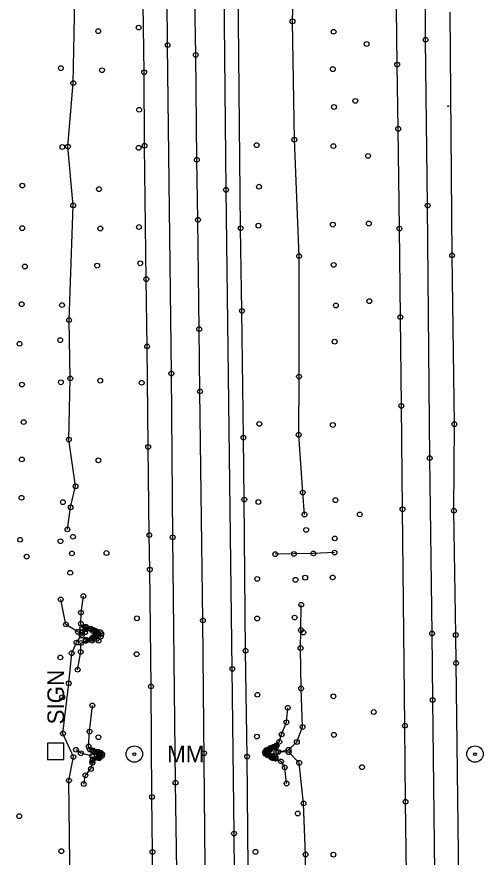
# Model space of a CAD drawing. Extents: x 20503438 to 20508873, y 7964251 to 7984667.
# Drawn here: x 20505333.3 to 20505528.3, y 7980569.8 to 7980921.4 of the extents above; entities that cross this region are included whole.
import ezdxf

# ---------------------------------------------------------------- set-up
doc = ezdxf.new("R2010")
doc.units = 0
for name, color, linetype in [('SurBreakLine', 7, 'Continuous'), ('SurConcreteSlab', 7, 'Continuous'), ('SurControl', 7, 'Continuous'), ('SurDikeDam', 7, 'Continuous'), ('SurDrainageArrowDown', 7, 'Continuous'), ('SurDrainageArrowUp', 7, 'Continuous'), ('SurEdgeRoadPaved', 7, 'Continuous'), ('SurEdgeShoulderPaved', 7, 'Continuous'), ('SurPointsNonDTM', 7, 'Continuous'), ('SurRoadPoints', 7, 'Continuous'), ('SurSurveyPoints', 7, 'Continuous')]:
    doc.layers.add(name, color=color, linetype=linetype)

msp = doc.modelspace()

# ---------------------------------------------------------------- linework, layer by layer
at = {"layer": 'SurBreakLine'}
for points in [[(20505502.82, 7979928.73), (20505501.16, 7980094.42), (20505500.7, 7980131.63), (20505500.35, 7980155.21), (20505500.03, 7980203.28), (20505500, 7980206.06), (20505499.27, 7980271.76), (20505498.89, 7980315.07), (20505498.72, 7980329.42), (20505496.74, 7980509.09), (20505496.18, 7980562.37), (20505495.83, 7980592.98), (20505495.56, 7980624.79), (20505494.56, 7980715.32), (20505494.07, 7980758.55), (20505493.65, 7980795.75), (20505493.28, 7980832.76), (20505492.74, 7980874.49), (20505492.33, 7980901.35), (20505491.27, 7980994.69)], [(20505418.93, 7979912.11), (20505417.39, 7980020.09), (20505416.54, 7980111.44), (20505416.16, 7980148.77), (20505415.87, 7980185.54), (20505415.61, 7980219.83), (20505414.98, 7980273.06), (20505413.7, 7980378.2), (20505413.25, 7980444.28), (20505412.62, 7980505.63), (20505412.46, 7980535.27), (20505412.01, 7980566.27), (20505411.1, 7980668.83), (20505409.87, 7980764.66), (20505409.52, 7980790.7), (20505409.02, 7980836.41), (20505408.56, 7980861.54), (20505408.11, 7980905.42), (20505407.63, 7980936.71)], [(20505358.71, 7980648.21), (20505360, 7980655.66), (20505360.09, 7980659.38), (20505362.08, 7980660.24), (20505364.7, 7980660.36), (20505367.46, 7980660.33), (20505368.33, 7980662.02), (20505368.64, 7980663.15), (20505368.18, 7980663.96), (20505366.63, 7980664.31), (20505365.38, 7980664.88), (20505364.19, 7980665.38), (20505362.16, 7980666.15), (20505362, 7980665.95), (20505360.66, 7980665.7), (20505360.07, 7980667.46), (20505360.12, 7980672.1), (20505361.13, 7980679.01)], [(20505361.28, 7980600.4), (20505361.96, 7980604.07), (20505364.25, 7980606.68), (20505364.86, 7980609.23), (20505364.89, 7980610.12), (20505367.74, 7980611.22), (20505368.79, 7980612.07), (20505368.96, 7980612.91), (20505368.3, 7980613.48), (20505367.34, 7980613.87), (20505363.86, 7980614.85), (20505363.29, 7980616.15), (20505363.69, 7980622.33), (20505364.86, 7980633.26)], [(20505446.07, 7980600.62), (20505445.32, 7980607.33), (20505443.76, 7980609.84), (20505441.48, 7980610.99), (20505440.46, 7980611.13), (20505439.6, 7980611.64), (20505438.2, 7980612.4), (20505437.31, 7980612.9), (20505437.04, 7980613.51), (20505437.24, 7980614.14), (20505437.83, 7980614.62), (20505439.22, 7980615.41), (20505440.71, 7980615.96), (20505441.56, 7980616.27), (20505441.96, 7980616.57), (20505443.03, 7980618.07), (20505444.02, 7980621.16), (20505446.03, 7980626.22), (20505446.58, 7980632.29)]]:
    msp.add_lwpolyline(points, dxfattribs=at)
at = {"layer": 'SurConcreteSlab'}
for points in [[(20505362.13, 7980665.18), (20505364.94, 7980664.43), (20505366.25, 7980664), (20505366.39, 7980663.87), (20505366.57, 7980663.36), (20505366.54, 7980662.54), (20505366.04, 7980662.17), (20505365.06, 7980661.69), (20505362.14, 7980660.73), (20505362.16, 7980660.37), (20505364.45, 7980661.16), (20505366.09, 7980661.88), (20505366.62, 7980662.49), (20505366.74, 7980663.12), (20505366.58, 7980663.81), (20505365.94, 7980664.48), (20505364.28, 7980665.11), (20505362.24, 7980665.82)], [(20505365.18, 7980610.75), (20505366.99, 7980611.4), (20505367.7, 7980611.85), (20505367.87, 7980612.49), (20505367.74, 7980613), (20505367.34, 7980613.43), (20505366.39, 7980613.7), (20505364.98, 7980614.1), (20505364.97, 7980614.48), (20505366.86, 7980613.86), (20505367.61, 7980613.5), (20505367.88, 7980613.02), (20505368, 7980612.17), (20505367.71, 7980611.62), (20505367.3, 7980611.28), (20505365.04, 7980610.34)], [(20505441.32, 7980611.16), (20505439.47, 7980611.95), (20505438.17, 7980612.56), (20505437.89, 7980613.27), (20505437.71, 7980613.86), (20505437.99, 7980614.33), (20505438.4, 7980614.76), (20505440.2, 7980615.76), (20505441.39, 7980616.14), (20505441.47, 7980615.66), (20505439.29, 7980614.82), (20505438.37, 7980614.41), (20505437.87, 7980613.99), (20505437.93, 7980613.38), (20505438.58, 7980612.75), (20505439.73, 7980612.28), (20505441.43, 7980611.75)]]:
    msp.add_lwpolyline(points, close=True, dxfattribs=at)
at = {"layer": 'SurControl'}
msp.add_circle((20505513.64, 7980883.97), 0.15, dxfattribs=at)
at = {"layer": 'SurDikeDam'}
msp.add_lwpolyline([(20505466.15, 7980697.22), (20505457.28, 7980696.87), (20505449.13, 7980696.65), (20505441.36, 7980696.54)], dxfattribs=at)
at = {"layer": 'SurDrainageArrowDown'}
for points in [[(20505453.57, 7980713.15), (20505452.85, 7980722.32), (20505451.14, 7980746.49), (20505451.29, 7980770.86), (20505451.3, 7980821.26), (20505449.33, 7980869.96), (20505448.57, 7980919.46), (20505450.46, 7980991.55), (20505449.17, 7981063.61)], [(20505354.44, 7980706.92), (20505355.74, 7980716.15), (20505357.83, 7980724.94), (20505355.05, 7980744.47), (20505355.64, 7980770.07), (20505355.13, 7980794.5), (20505356.84, 7980842.47), (20505354.66, 7980867.05), (20505356.9, 7980893.61), (20505357.84, 7980942.6)], [(20505355.65, 7980555.76), (20505355.07, 7980601.84), (20505356.93, 7980611.74), (20505352.58, 7980621.54), (20505355, 7980642.51), (20505356.23, 7980655.13), (20505358.24, 7980659.58), (20505360.38, 7980662.52), (20505361.8, 7980663.84)], [(20505364.74, 7980611.99), (20505360.03, 7980613.25), (20505358.03, 7980614.74)], [(20505455.75, 7980440.25), (20505455.16, 7980491.26), (20505454.21, 7980542.27), (20505454.01, 7980570.91), (20505453.19, 7980592.26), (20505451.34, 7980609.26), (20505446.96, 7980613.69), (20505442.6, 7980613.8)]]:
    msp.add_lwpolyline(points, dxfattribs=at)
at = {"layer": 'SurDrainageArrowUp'}
for points in [[(20505360.32, 7980663.64), (20505358.81, 7980664.05), (20505353.81, 7980667.17), (20505351.64, 7980677.61)], [(20505441.76, 7980613.76), (20505446.87, 7980614.71), (20505450.36, 7980617.97), (20505452.79, 7980624.27), (20505452.14, 7980640.35), (20505451.9, 7980657.28), (20505452.07, 7980664.77), (20505452.22, 7980675.39)]]:
    msp.add_lwpolyline(points, dxfattribs=at)
at = {"layer": 'SurEdgeRoadPaved'}
for points in [[(20505407.01, 7979911.27), (20505405.62, 7980027.77), (20505404.97, 7980099.48), (20505403.88, 7980170.44), (20505403.36, 7980242.05), (20505402.88, 7980278.12), (20505401.81, 7980377.51), (20505401.55, 7980417.01), (20505401.15, 7980456.16), (20505400.97, 7980492.44), (20505400.5, 7980529.47), (20505400.23, 7980564.23), (20505399.63, 7980600.95), (20505398.46, 7980703.6), (20505397.89, 7980772.13), (20505396.33, 7980909.55), (20505395.68, 7980987.14)], [(20505433.05, 7979713.21), (20505430.71, 7979940.08), (20505429.71, 7980003.79), (20505429.2, 7980048.09), (20505428.22, 7980153.85), (20505427.89, 7980202.23), (20505427.07, 7980275.05), (20505425.92, 7980355.65), (20505424.11, 7980579.66), (20505423.37, 7980648.54), (20505420.77, 7980848.98), (20505419.47, 7980988.86)], [(20505516.05, 7979812.06), (20505513.49, 7980050.6), (20505513.24, 7980088.09), (20505512.01, 7980188.2), (20505511.47, 7980251.39), (20505511.41, 7980259.84), (20505510.87, 7980304.58), (20505510.69, 7980324.76), (20505510.08, 7980377.01), (20505508.54, 7980527.34), (20505507.19, 7980635.55), (20505506.92, 7980663.36), (20505505.94, 7980736.75), (20505505.07, 7980842.4), (20505504.2, 7980911.75), (20505503.99, 7980947.26)]]:
    msp.add_lwpolyline(points, dxfattribs=at)
at = {"layer": 'SurEdgeShoulderPaved'}
for points in [[(20505436.58, 7979926.47), (20505435.19, 7980029.33), (20505434.04, 7980149.6), (20505433.33, 7980234.89), (20505431.57, 7980392.66), (20505429.57, 7980611.85), (20505428.94, 7980656.15), (20505428.39, 7980719.4), (20505428.03, 7980745.3), (20505427.42, 7980798.3), (20505426.86, 7980832.89), (20505425.41, 7980977.21)], [(20505390.37, 7980538.15), (20505390.02, 7980571.99), (20505389.8, 7980594.97), (20505389.39, 7980641.21), (20505388.9, 7980690.08), (20505388.66, 7980704.55), (20505388.19, 7980741.4), (20505387.76, 7980783.47), (20505387.42, 7980811.61), (20505386.69, 7980867.4), (20505386.54, 7980898.14), (20505386.17, 7980926.55)], [(20505525.14, 7979901.72), (20505524.22, 7979974.98), (20505523.61, 7980046.77), (20505523.09, 7980083.23), (20505522.65, 7980131.31), (20505521.87, 7980192.78), (20505521.53, 7980266.52), (20505520.61, 7980336.57), (20505519.29, 7980467.56), (20505518.75, 7980508.1), (20505518.14, 7980560.14), (20505516.98, 7980650.97), (20505516.82, 7980662.74), (20505516.06, 7980714.7), (20505516.27, 7980750.94), (20505515.28, 7980821.55), (20505514.45, 7980923.25)]]:
    msp.add_lwpolyline(points, dxfattribs=at)
at = {"layer": 'SurPointsNonDTM'}
for centre in [(20505453.07, 7980663.77), (20505411.59, 7980613.28)]:
    msp.add_circle(centre, 1, dxfattribs=at)
at = {"layer": 'SurRoadPoints'}
msp.add_lwpolyline([(20505353, 7980614.11), (20505353, 7980614.11), (20505353, 7980617.54), (20505346.14, 7980617.54), (20505346.14, 7980610.68), (20505353, 7980610.68), (20505353, 7980614.11)], dxfattribs=at)
for centre, radius in [((20505382.42, 7980612.93), 3.43), ((20505524.87, 7980612.93), 3.43), ((20505382.42, 7980612.93), 0.571), ((20505524.87, 7980612.93), 0.571)]:
    msp.add_circle(centre, radius, dxfattribs=at)
at = {"layer": 'SurSurveyPoints'}
for centre in [(20505448.57, 7980919.46), (20505384.23, 7980916.84), (20505367.33, 7980915.36), (20505465.76, 7980915.09), (20505396.33, 7980909.55), (20505479.55, 7980909.97), (20505504.2, 7980911.75), (20505408.11, 7980905.42), (20505351.71, 7980899.87), (20505368.9, 7980899.01), (20505386.54, 7980898.14), (20505465.43, 7980899.46), (20505492.33, 7980901.35), (20505356.9, 7980893.61), (20505474.84, 7980886.18), (20505384.44, 7980882.46), (20505465.91, 7980883.63), (20505492.74, 7980874.49), (20505449.33, 7980869.96), (20505352.33, 7980866.88), (20505354.66, 7980867.05), (20505384.22, 7980866.55), (20505386.69, 7980867.4), (20505433.58, 7980867.65), (20505465.68, 7980867.27), (20505480.16, 7980863.17), (20505408.56, 7980861.54), (20505335.56, 7980850.74), (20505367.62, 7980849.24), (20505420.77, 7980848.98), (20505434.56, 7980850.28), (20505356.84, 7980842.47), (20505505.07, 7980842.4), (20505409.02, 7980836.41), (20505480.48, 7980834.88), (20505335.54, 7980832.93), (20505368.2, 7980832.78), (20505384.34, 7980833.41), (20505426.86, 7980832.89), (20505434.3, 7980833.97), (20505465.43, 7980834.41), (20505493.28, 7980832.76), (20505451.3, 7980821.26), (20505515.28, 7980821.55), (20505366.87, 7980817.26), (20505384.88, 7980818.24), (20505465.78, 7980817.57), (20505336.64, 7980816.91), (20505387.42, 7980811.61), (20505335.29, 7980801.14), (20505352.18, 7980800.74), (20505466.71, 7980800.57), (20505480.68, 7980802.38), (20505427.42, 7980798.3), (20505355.13, 7980794.5), (20505493.65, 7980795.75), (20505409.52, 7980790.7), (20505351.42, 7980786.08), (20505466.2, 7980785.45), (20505334.42, 7980784.56), (20505387.76, 7980783.47), (20505397.89, 7980772.13), (20505351.71, 7980768.45), (20505355.64, 7980770.07), (20505368.16, 7980769.14), (20505385.48, 7980768.26), (20505451.29, 7980770.86), (20505335.42, 7980767.49), (20505409.87, 7980764.66), (20505494.07, 7980758.55), (20505336.13, 7980751.79), (20505434.68, 7980751.06), (20505465.43, 7980750.6), (20505516.27, 7980750.94), (20505355.05, 7980744.47), (20505428.03, 7980745.3), (20505451.14, 7980746.49), (20505388.19, 7980741.4), (20505335.38, 7980736.18), (20505505.94, 7980736.75), (20505367.37, 7980735.8), (20505357.83, 7980724.94), (20505452.85, 7980722.32), (20505335.22, 7980720.14), (20505428.39, 7980719.4), (20505466.52, 7980719.13), (20505352.53, 7980718.31), (20505355.74, 7980716.15), (20505434.28, 7980718.37), (20505494.56, 7980715.32), (20505453.57, 7980713.15), (20505476.69, 7980713.18), (20505516.06, 7980714.7), (20505354.44, 7980706.92), (20505388.66, 7980704.55), (20505454.26, 7980706.7), (20505334.65, 7980702.59), (20505351.55, 7980701.96), (20505356.78, 7980703.83), (20505398.46, 7980703.6), (20505466.22, 7980703.15), (20505337.37, 7980695.53), (20505356.32, 7980696.86), (20505370.79, 7980697.03), (20505441.36, 7980696.54), (20505449.13, 7980696.65), (20505457.28, 7980696.87), (20505466.15, 7980697.22), (20505355.57, 7980688.78), (20505388.9, 7980690.08), (20505433.82, 7980686.21), (20505449.8, 7980685.81), (20505453.85, 7980686.72), (20505465.35, 7980686.81), (20505351.64, 7980677.61), (20505361.13, 7980679.01), (20505452.22, 7980675.39), (20505360.12, 7980672.1), (20505383.48, 7980669.7), (20505433.79, 7980669.64), (20505449.44, 7980670.04), (20505353.81, 7980667.17), (20505360.07, 7980667.46), (20505362, 7980665.95), (20505362.16, 7980666.15), (20505411.1, 7980668.83), (20505358.81, 7980664.05), (20505360.32, 7980663.64), (20505360.38, 7980662.52), (20505360.66, 7980665.7), (20505361.8, 7980663.84), (20505362.13, 7980665.18), (20505362.24, 7980665.82), (20505364.19, 7980665.38), (20505364.28, 7980665.11), (20505364.94, 7980664.43), (20505365.38, 7980664.88), (20505365.94, 7980664.48), (20505366.25, 7980664), (20505366.39, 7980663.87), (20505366.54, 7980662.54), (20505366.57, 7980663.36), (20505366.58, 7980663.81), (20505366.62, 7980662.49), (20505366.63, 7980664.31), (20505366.74, 7980663.12), (20505368.18, 7980663.96), (20505368.64, 7980663.15), (20505452.07, 7980664.77), (20505506.92, 7980663.36), (20505516.82, 7980662.74), (20505358.24, 7980659.58), (20505360.09, 7980659.38), (20505362.08, 7980660.24), (20505362.14, 7980660.73), (20505362.16, 7980660.37), (20505364.45, 7980661.16), (20505364.7, 7980660.36), (20505365.06, 7980661.69), (20505366.04, 7980662.17), (20505366.09, 7980661.88), (20505367.46, 7980660.33), (20505368.33, 7980662.02), (20505360, 7980655.66), (20505428.94, 7980656.15), (20505451.9, 7980657.28), (20505351.47, 7980653.34), (20505356.23, 7980655.13), (20505383.37, 7980654.72), (20505423.37, 7980648.54), (20505516.98, 7980650.97), (20505358.71, 7980648.21), (20505355, 7980642.51), (20505389.39, 7980641.21), (20505433.87, 7980637.75), (20505452.14, 7980640.35), (20505352.25, 7980636.65), (20505465.68, 7980637.09), (20505507.19, 7980635.55), (20505364.86, 7980633.26), (20505446.58, 7980632.29), (20505482.54, 7980630.5), (20505446.03, 7980626.22), (20505452.79, 7980624.27), (20505495.56, 7980624.79), (20505352.58, 7980621.54), (20505363.69, 7980622.33), (20505433.66, 7980620.23), (20505444.02, 7980621.16), (20505465.86, 7980620.97), (20505367.4, 7980619.98), (20505443.03, 7980618.07), (20505450.36, 7980617.97), (20505358.03, 7980614.74), (20505360.03, 7980613.25), (20505363.29, 7980616.15), (20505363.86, 7980614.85), (20505364.97, 7980614.48), (20505364.98, 7980614.1), (20505366.39, 7980613.7), (20505366.86, 7980613.86), (20505367.34, 7980613.87), (20505367.34, 7980613.43), (20505367.61, 7980613.5), (20505368.3, 7980613.48), (20505437.04, 7980613.51), (20505437.24, 7980614.14), (20505437.71, 7980613.86), (20505437.83, 7980614.62), (20505437.87, 7980613.99), (20505437.89, 7980613.27), (20505437.93, 7980613.38), (20505437.99, 7980614.33), (20505438.37, 7980614.41), (20505438.4, 7980614.76), (20505439.22, 7980615.41), (20505439.29, 7980614.82), (20505440.2, 7980615.76), (20505440.71, 7980615.96), (20505441.39, 7980616.14), (20505441.47, 7980615.66), (20505441.56, 7980616.27), (20505441.76, 7980613.76), (20505441.96, 7980616.57), (20505442.6, 7980613.8), (20505446.87, 7980614.71), (20505446.96, 7980613.69), (20505356.93, 7980611.74), (20505364.74, 7980611.99), (20505364.89, 7980610.12), (20505365.04, 7980610.34), (20505365.18, 7980610.75), (20505366.99, 7980611.4), (20505367.3, 7980611.28), (20505367.7, 7980611.85), (20505367.71, 7980611.62), (20505367.74, 7980613), (20505367.74, 7980611.22), (20505367.87, 7980612.49), (20505367.88, 7980613.02), (20505368, 7980612.17), (20505368.79, 7980612.07), (20505368.96, 7980612.91), (20505429.57, 7980611.85), (20505437.31, 7980612.9), (20505438.17, 7980612.56), (20505438.2, 7980612.4), (20505438.58, 7980612.75), (20505439.47, 7980611.95), (20505439.6, 7980611.64), (20505439.73, 7980612.28), (20505440.46, 7980611.13), (20505441.32, 7980611.16), (20505441.43, 7980611.75), (20505441.48, 7980610.99), (20505443.76, 7980609.84), (20505364.25, 7980606.68), (20505364.86, 7980609.23), (20505445.32, 7980607.33), (20505451.34, 7980609.26), (20505477.62, 7980607.43), (20505361.96, 7980604.07), (20505355.07, 7980601.84), (20505361.28, 7980600.4), (20505399.63, 7980600.95), (20505446.07, 7980600.62), (20505389.8, 7980594.97), (20505453.19, 7980592.26), (20505495.83, 7980592.98), (20505334.27, 7980586.95), (20505450.76, 7980588.06), (20505424.11, 7980579.66), (20505351.88, 7980572.31), (20505390.02, 7980571.99), (20505433.08, 7980572.02), (20505454.01, 7980570.91), (20505465.68, 7980570.83)]:
    msp.add_circle(centre, 1, dxfattribs=at)

# ---------------------------------------------------------------- texts
at = {"layer": 'SurRoadPoints'}
for s, rotation, p in [('SIGN', 90, (20505353.07, 7980625.32)), ('MM', 360, (20505396.13, 7980609.44))]:
    msp.add_text(s, height=6.995, rotation=rotation, dxfattribs=at).set_placement(p)

doc.saveas('drawing.dxf')
